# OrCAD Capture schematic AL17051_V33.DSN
size Custom; title: AL17051, ULTRA LOW STANDBY POWER HV BUCK CONVERTER; rev: 1.0; note: DS44934_REV.2-2
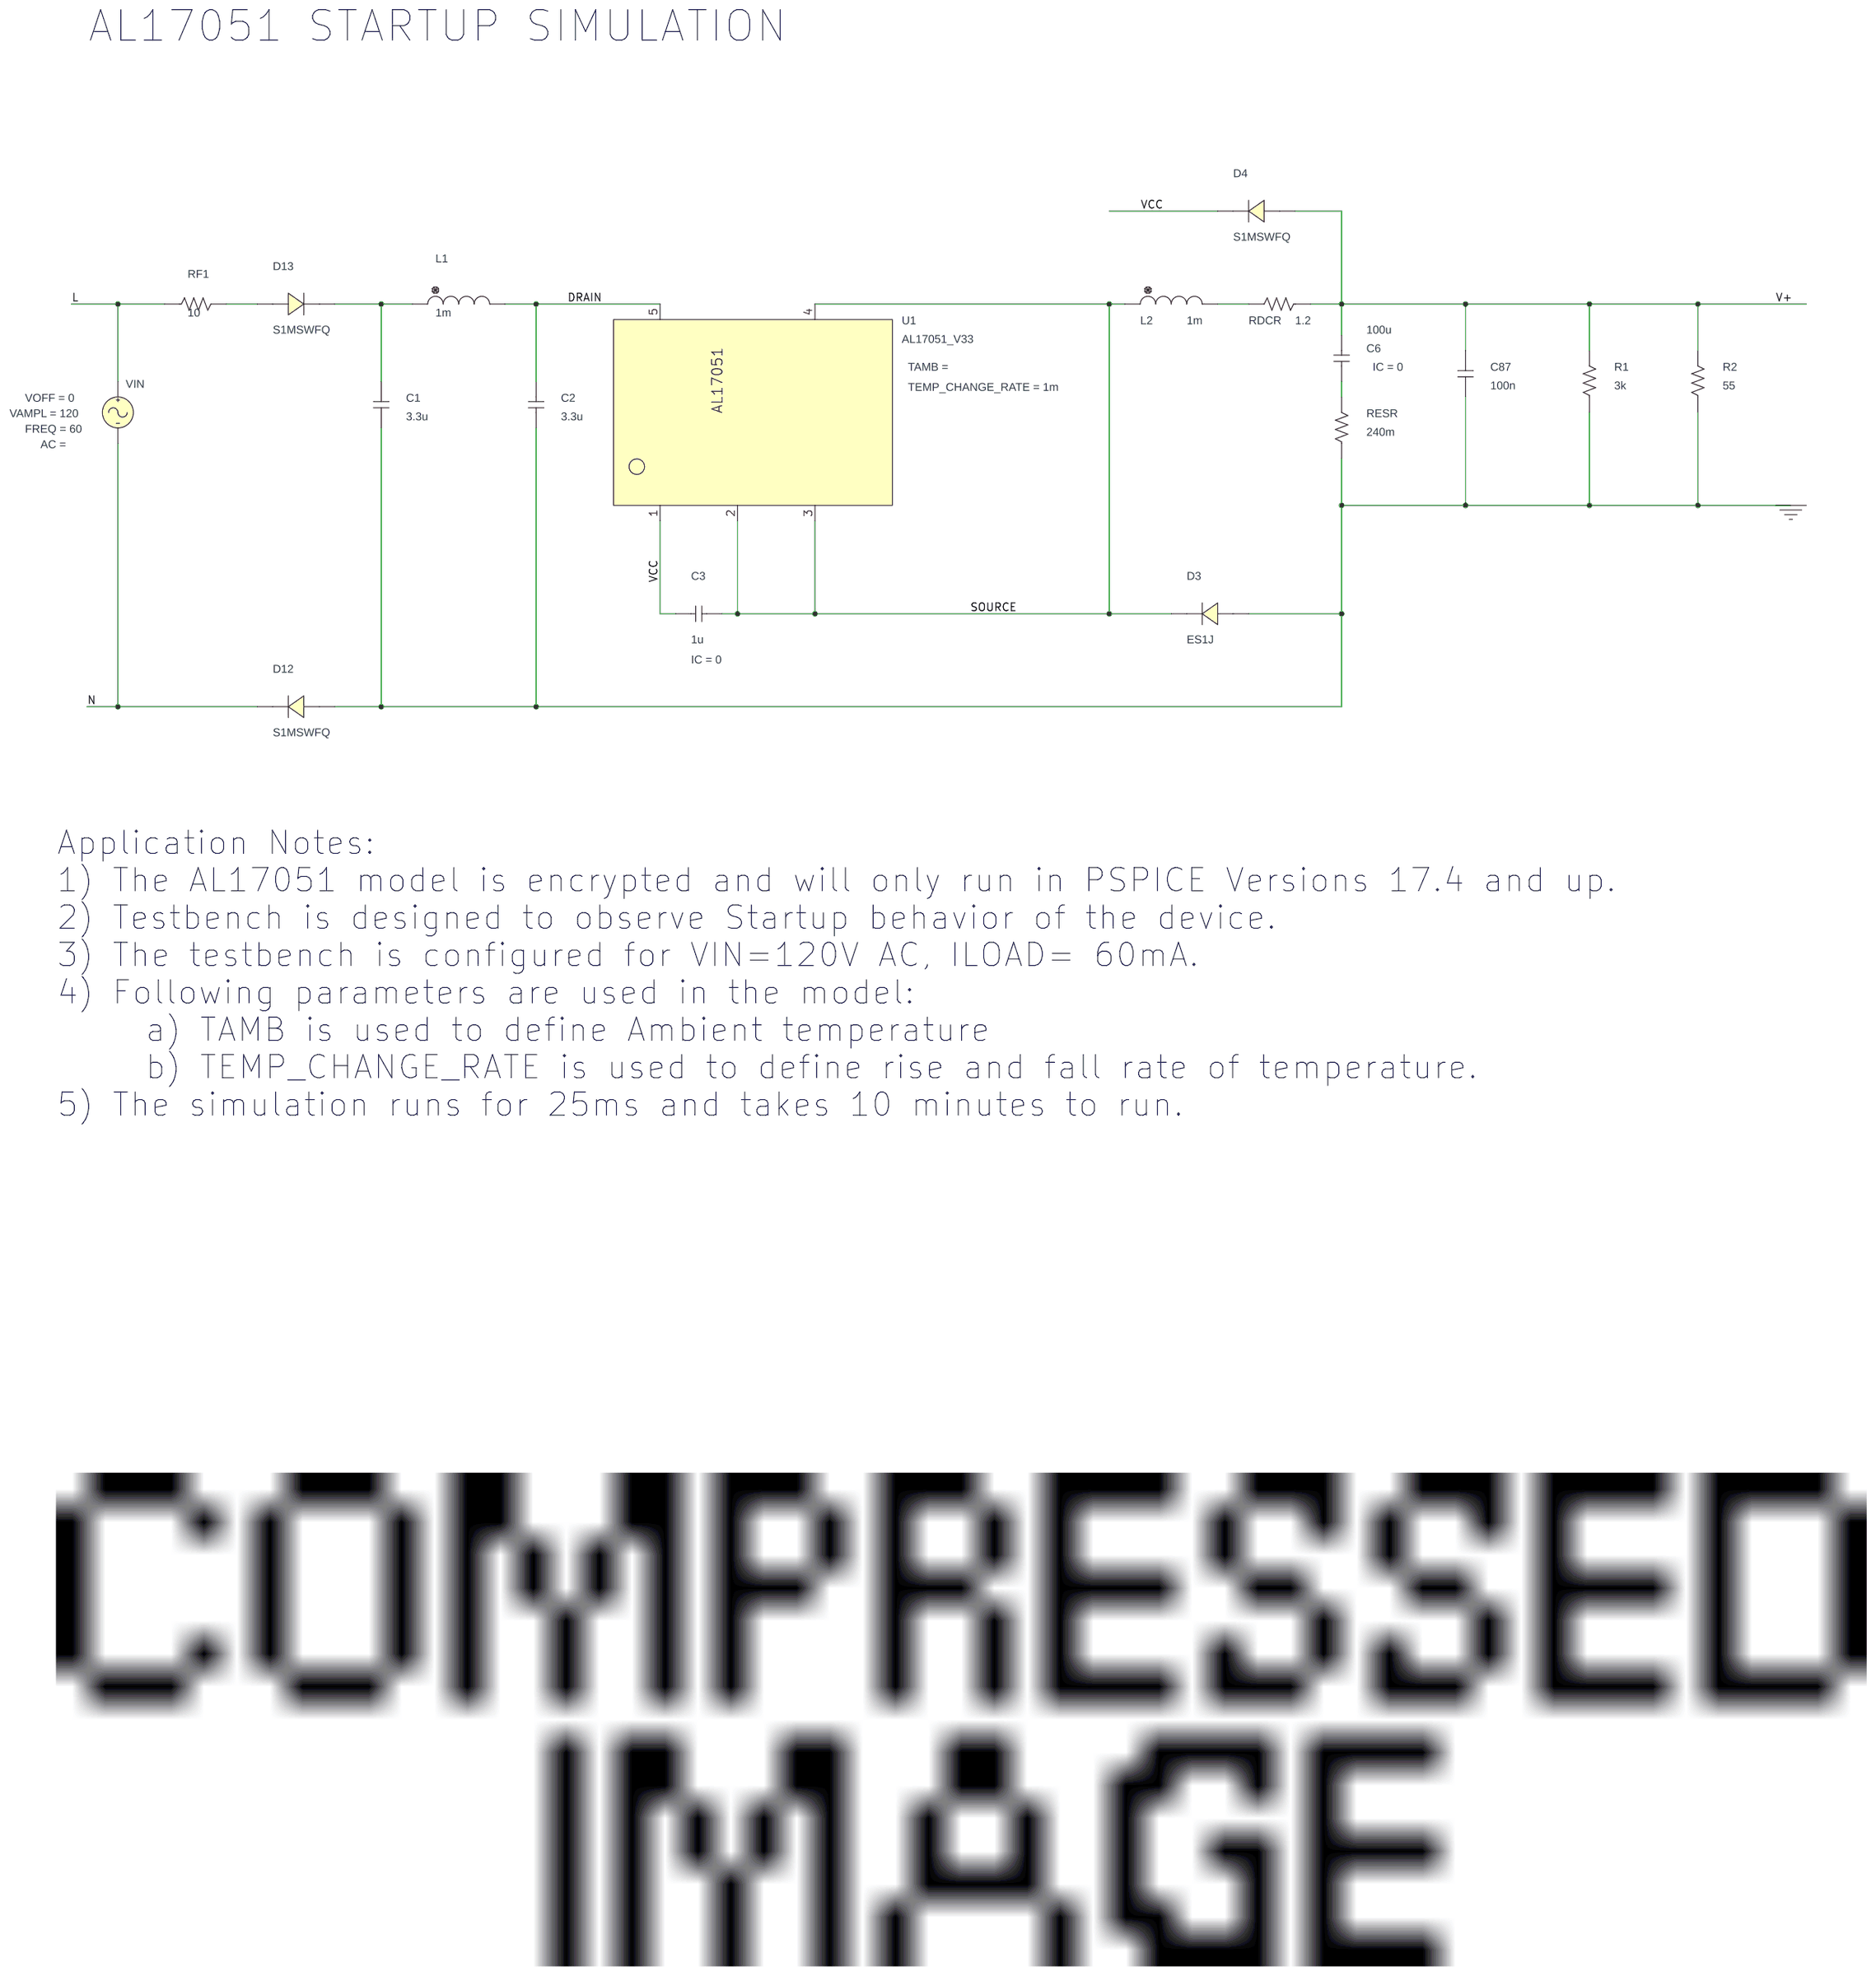
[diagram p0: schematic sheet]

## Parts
C1  3.3u  [RAD/CK05]
C2  3.3u  [RAD/CK05]
C3  1u  [RAD/CK05]
C6  100u  [RAD/CK05]
C87  100n  [RAD/CK05]
D3  ES1J
D4  S1MSWFQ
D12  S1MSWFQ
D13  S1MSWFQ
L1  1m  [DISC/.350x.175/LS.200x.100/.034]
L2  1m  [DISC/.350x.175/LS.200x.100/.034]
R1  3k  [AX/RC05]
R2  55  [AX/RC05]
RDCR  1.2  [AX/RC05]
RESR  240m  [AX/RC05]
RF1  10  [AX/RC05]
U1  AL17051_V33
VIN  VSIN

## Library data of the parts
C1 C2 C87 = C
C3 C6 = C: IC: 0
D3 = ES1J
D4 D12 D13 = S1MSWFQ
L1 L2 = L
R1 R2 RDCR RESR RF1 = R
U1 = AL17051_V33: TEMP_CHANGE_RATE: 1m
VIN = VSIN: FREQ: 60; VAMPL: 120; VOFF: 0

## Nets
VCC: C3.1 D4.2 U1.1(VCC)
0: C1.1 C2.1 C87.1 D3.1 D12.1 R1.1 R2.1 RESR.1
DRAIN: C2.2 L1.2 U1.5(DRAIN)
L: RF1.1 VIN.1(+)
N: D12.2 VIN.2(-)
SOURCE: C3.2 D3.2 L2.1 U1.2(SOURCE_1) U1.3(SOURCE_2) U1.4(SOURCE_3)
V+: C6.1 C87.2 D4.1 R1.2 R2.2 RDCR.1
N16427049: D13.1 RF1.2
N16427055: C1.2 D13.2 L1.1
N16433897: L2.2 RDCR.2
N16434007: C6.2 RESR.2

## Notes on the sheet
- AL17051 STARTUP SIMULATION
- Application Notes:
  1) The AL17051 model is encrypted and will only run in PSPICE Versions 17.4 and up.
  2) Testbench is designed to observe Startup behavior of the device.
  3) The testbench is configured for VIN=120V AC, ILOAD= 60mA.
  4) Following parameters are used in the model:
       a) TAMB is used to define Ambient temperature
       b) TEMP_CHANGE_RATE is used to define rise and fall rate of temperature.
  5) The simulation runs for 25ms and takes 10 minutes to run.
